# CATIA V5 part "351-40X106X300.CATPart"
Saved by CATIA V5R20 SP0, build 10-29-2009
Part number: 351-40X106X300
Definition: NONE
Nomenclature: 351-40X106X300
Source: Unknown
Description: 351-40X106X300
Bounding box of the stored display mesh (mm): x -8 to 292, y -26 to 26, z -26 to 26
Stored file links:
  C:\Users\Utente\Desktop\IO LAVORO\3D X SITO CF\X SITO\PLASTICA\351\351-40X106X300.CATPart

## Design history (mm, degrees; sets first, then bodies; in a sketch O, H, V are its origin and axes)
Body1 "351-40X106X300" (main body)
  Solid1: solid without history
